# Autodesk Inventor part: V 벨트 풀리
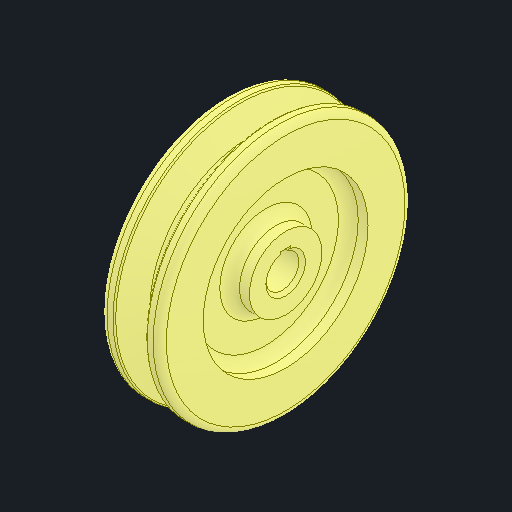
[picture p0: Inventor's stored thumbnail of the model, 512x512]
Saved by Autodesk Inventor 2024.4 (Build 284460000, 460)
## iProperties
Created: 2025-10
Part Number: V 벨트 풀리
Material: 강철, 주조
Document SubType Name: Modeling
Designer: user
Density: 7.85 g/cm^3
Appearance: 기본값
Author: jhkim
Sending System: Autodesk Inventor 2026
Preprocessor: ST-DEVELOPER v20.1
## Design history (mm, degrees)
feature "솔리드1"
node "솔리드2"
